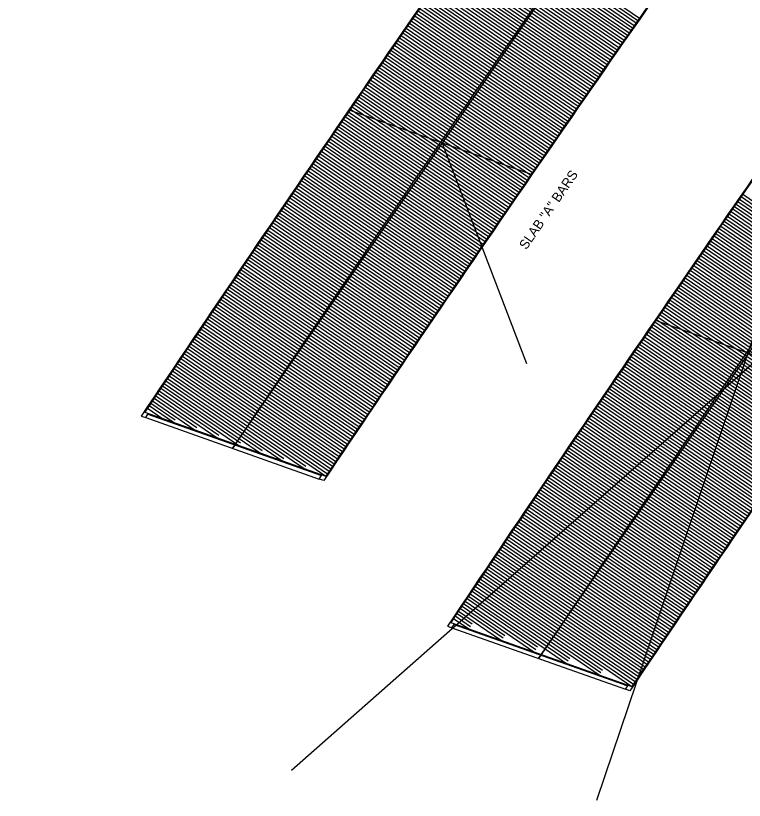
# Model space of a CAD drawing. Extents: x 2378999 to 2381348, y 331302 to 333122.
# Drawn here: x 2379615.5 to 2379768, y 332290.5 to 332454.8 of the extents above; entities that cross this region are included whole.
import ezdxf

# ---------------------------------------------------------------- set-up
doc = ezdxf.new("R2010")
doc.units = 0
for name, color, linetype in [('Mis Work Point CELL', 7, 'Continuous'), ('Old_Level_8', 7, 'Continuous'), ('P_SMU_Concrete_Barrier_Rail', 7, 'Continuous'), ('P_SMU_Mis_Long_Chord', 7, 'Continuous'), ('P_SMU_Rebar_B_Bar', 7, 'Continuous'), ('P_SMU_Rebar_K_Bar', 7, 'Continuous'), ('Plan Sheet CELL', 7, 'Continuous'), ('Scratch_Level_0', 7, 'Continuous'), ('Sup Concrete Slab Lines', 7, 'Continuous'), ('Text', 7, 'Continuous')]:
    doc.layers.add(name, color=color, linetype=linetype)

msp = doc.modelspace()

# ---------------------------------------------------------------- linework, layer by layer
at = {"layer": 'Mis Work Point CELL'}
for p, q in [((2379685.3, 332435.09), (2379723.61, 332421.53)), ((2379749.38, 332391.06), (2379787.69, 332377.5))]:
    msp.add_line(p, q, dxfattribs=at)
at = {"layer": 'Old_Level_8'}
for p, q in [((2379713.66, 332475.82), (2379745.74, 332453.79)), ((2379714.02, 332476.34), (2379746.09, 332454.3)), ((2379712.23, 332473.77), (2379744.31, 332451.73)), ((2379712.59, 332474.28), (2379744.67, 332452.25)), ((2379712.95, 332474.8), (2379745.02, 332452.76)), ((2379713.3, 332475.31), (2379745.38, 332453.27)), ((2379711.16, 332472.23), (2379743.24, 332450.19)), ((2379711.52, 332472.75), (2379743.59, 332450.71)), ((2379711.87, 332473.26), (2379743.95, 332451.22)), ((2379710.09, 332470.69), (2379742.17, 332448.66)), ((2379710.45, 332471.21), (2379742.52, 332449.17)), ((2379710.8, 332471.72), (2379742.88, 332449.68)), ((2379709.02, 332469.15), (2379741.1, 332447.12)), ((2379709.38, 332469.67), (2379741.45, 332447.63)), ((2379709.73, 332470.18), (2379741.81, 332448.14)), ((2379707.95, 332467.61), (2379740.03, 332445.58)), ((2379708.31, 332468.13), (2379740.38, 332446.09)), ((2379708.66, 332468.64), (2379740.74, 332446.6)), ((2379706.53, 332465.56), (2379738.6, 332443.52)), ((2379706.88, 332466.07), (2379738.96, 332444.03)), ((2379707.24, 332466.59), (2379739.31, 332444.55)), ((2379707.6, 332467.1), (2379739.67, 332445.06)), ((2379705.46, 332464.02), (2379737.53, 332441.98)), ((2379705.81, 332464.53), (2379737.89, 332442.49)), ((2379706.17, 332465.05), (2379738.25, 332443.01)), ((2379704.39, 332462.48), (2379736.47, 332440.44)), ((2379704.75, 332462.99), (2379736.82, 332440.95)), ((2379705.1, 332463.5), (2379737.18, 332441.47)), ((2379703.32, 332460.94), (2379735.4, 332438.9)), ((2379703.68, 332461.45), (2379735.75, 332439.41)), ((2379704.03, 332461.96), (2379736.11, 332439.93)), ((2379702.25, 332459.39), (2379734.33, 332437.36)), ((2379702.61, 332459.91), (2379734.69, 332437.87)), ((2379702.97, 332460.42), (2379735.04, 332438.38)), ((2379700.83, 332457.34), (2379732.91, 332435.3)), ((2379701.19, 332457.85), (2379733.26, 332435.81)), ((2379701.54, 332458.37), (2379733.62, 332436.33)), ((2379701.9, 332458.88), (2379733.98, 332436.84)), ((2379699.77, 332455.8), (2379731.84, 332433.76)), ((2379700.12, 332456.31), (2379732.2, 332434.27)), ((2379700.48, 332456.82), (2379732.55, 332434.79)), ((2379698.7, 332454.25), (2379730.78, 332432.22)), ((2379699.06, 332454.77), (2379731.13, 332432.73)), ((2379699.41, 332455.28), (2379731.49, 332433.24)), ((2379697.63, 332452.71), (2379729.71, 332430.67)), ((2379697.99, 332453.22), (2379730.07, 332431.19)), ((2379698.34, 332453.74), (2379730.42, 332431.7)), ((2379696.57, 332451.17), (2379728.65, 332429.13)), ((2379696.92, 332451.68), (2379729, 332429.64)), ((2379697.28, 332452.2), (2379729.36, 332430.16)), ((2379695.15, 332449.11), (2379727.23, 332427.07)), ((2379695.5, 332449.62), (2379727.58, 332427.59)), ((2379695.86, 332450.14), (2379727.94, 332428.1)), ((2379696.21, 332450.65), (2379728.29, 332428.62)), ((2379694.09, 332447.57), (2379726.16, 332425.53)), ((2379694.44, 332448.08), (2379726.52, 332426.04)), ((2379694.8, 332448.59), (2379726.87, 332426.56)), ((2379693.02, 332446.02), (2379725.1, 332423.98)), ((2379693.38, 332446.54), (2379725.45, 332424.5)), ((2379693.73, 332447.05), (2379725.81, 332425.01)), ((2379691.96, 332444.48), (2379724.03, 332422.44)), ((2379692.31, 332444.99), (2379724.39, 332422.95)), ((2379692.67, 332445.51), (2379724.74, 332423.47)), ((2379690.9, 332442.93), (2379722.97, 332420.9)), ((2379691.25, 332443.45), (2379723.33, 332421.41)), ((2379691.6, 332443.96), (2379723.68, 332421.93)), ((2379689.48, 332440.87), (2379721.56, 332418.84)), ((2379689.83, 332441.39), (2379721.91, 332419.35)), ((2379690.19, 332441.9), (2379722.26, 332419.87)), ((2379690.54, 332442.42), (2379722.62, 332420.38)), ((2379688.42, 332439.33), (2379720.49, 332417.29)), ((2379688.77, 332439.84), (2379720.85, 332417.81)), ((2379689.13, 332440.36), (2379721.2, 332418.32)), ((2379687.36, 332437.78), (2379719.43, 332415.74)), ((2379687.71, 332438.3), (2379719.79, 332416.26)), ((2379688.06, 332438.81), (2379720.14, 332416.77)), ((2379686.29, 332436.24), (2379718.37, 332414.2)), ((2379686.65, 332436.75), (2379718.72, 332414.71)), ((2379687, 332437.27), (2379719.08, 332415.23)), ((2379685.23, 332434.69), (2379717.31, 332412.65)), ((2379685.59, 332435.21), (2379717.66, 332413.17)), ((2379685.94, 332435.72), (2379718.02, 332413.68)), ((2379684.17, 332433.14), (2379716.25, 332411.11)), ((2379684.53, 332433.66), (2379716.6, 332411.62)), ((2379684.88, 332434.17), (2379716.96, 332412.14)), ((2379682.76, 332431.08), (2379714.84, 332409.04)), ((2379683.11, 332431.6), (2379715.19, 332409.56)), ((2379683.47, 332432.11), (2379715.54, 332410.08)), ((2379683.82, 332432.63), (2379715.9, 332410.59)), ((2379681.7, 332429.53), (2379713.78, 332407.5)), ((2379682.05, 332430.05), (2379714.13, 332408.01)), ((2379682.41, 332430.57), (2379714.48, 332408.53)), ((2379680.64, 332427.99), (2379712.72, 332405.95)), ((2379681, 332428.5), (2379713.07, 332406.47)), ((2379681.35, 332429.02), (2379713.42, 332406.98)), ((2379679.58, 332426.44), (2379711.66, 332404.4)), ((2379679.94, 332426.96), (2379712.01, 332404.92)), ((2379680.29, 332427.47), (2379712.37, 332405.43)), ((2379678.53, 332424.89), (2379710.6, 332402.85)), ((2379678.88, 332425.41), (2379710.95, 332403.37)), ((2379679.23, 332425.92), (2379711.31, 332403.89)), ((2379677.12, 332422.83), (2379709.19, 332400.79)), ((2379677.47, 332423.34), (2379709.54, 332401.31)), ((2379677.82, 332423.86), (2379709.9, 332401.82)), ((2379678.17, 332424.38), (2379710.25, 332402.34)), ((2379676.06, 332421.28), (2379708.13, 332399.24)), ((2379676.41, 332421.79), (2379708.49, 332399.76)), ((2379676.76, 332422.31), (2379708.84, 332400.27)), ((2379675, 332419.73), (2379707.08, 332397.69)), ((2379675.35, 332420.25), (2379707.43, 332398.21)), ((2379675.71, 332420.76), (2379707.78, 332398.72)), ((2379673.94, 332418.18), (2379706.02, 332396.14)), ((2379674.3, 332418.7), (2379706.37, 332396.66)), ((2379674.65, 332419.21), (2379706.73, 332397.18)), ((2379672.89, 332416.63), (2379704.96, 332394.59)), ((2379673.24, 332417.15), (2379705.32, 332395.11)), ((2379673.59, 332417.66), (2379705.67, 332395.63)), ((2379767.04, 332416.38), (2379799.11, 332394.34)), ((2379767.39, 332416.9), (2379799.47, 332394.86)), ((2379767.75, 332417.41), (2379799.82, 332395.37)), ((2379671.83, 332415.08), (2379703.91, 332393.04)), ((2379672.19, 332415.6), (2379704.26, 332393.56)), ((2379672.54, 332416.11), (2379704.61, 332394.08)), ((2379765.97, 332414.84), (2379798.04, 332392.8)), ((2379766.32, 332415.35), (2379798.4, 332393.32)), ((2379766.68, 332415.87), (2379798.76, 332393.83)), ((2379670.43, 332413.01), (2379702.5, 332390.98)), ((2379670.78, 332413.53), (2379702.85, 332391.49)), ((2379671.13, 332414.05), (2379703.21, 332392.01)), ((2379671.48, 332414.56), (2379703.56, 332392.53)), ((2379764.9, 332413.3), (2379796.98, 332391.26)), ((2379765.26, 332413.81), (2379797.33, 332391.77)), ((2379765.61, 332414.33), (2379797.69, 332392.29)), ((2379669.37, 332411.46), (2379701.45, 332389.43)), ((2379669.72, 332411.98), (2379701.8, 332389.94)), ((2379670.07, 332412.5), (2379702.15, 332390.46)), ((2379763.84, 332411.76), (2379795.91, 332389.72)), ((2379764.19, 332412.27), (2379796.27, 332390.23)), ((2379764.55, 332412.78), (2379796.62, 332390.75)), ((2379668.32, 332409.91), (2379700.39, 332387.88)), ((2379668.67, 332410.43), (2379700.75, 332388.39)), ((2379669.02, 332410.95), (2379701.1, 332388.91)), ((2379762.41, 332409.7), (2379794.49, 332387.66)), ((2379762.77, 332410.21), (2379794.85, 332388.18)), ((2379763.12, 332410.73), (2379795.2, 332388.69)), ((2379763.48, 332411.24), (2379795.56, 332389.2)), ((2379667.26, 332408.36), (2379699.34, 332386.33)), ((2379667.62, 332408.88), (2379699.69, 332386.84)), ((2379667.97, 332409.4), (2379700.04, 332387.36)), ((2379761.35, 332408.16), (2379793.42, 332386.12)), ((2379761.7, 332408.67), (2379793.78, 332386.63)), ((2379762.06, 332409.19), (2379794.14, 332387.15)), ((2379666.21, 332406.81), (2379698.29, 332384.77)), ((2379666.56, 332407.33), (2379698.64, 332385.29)), ((2379666.91, 332407.85), (2379698.99, 332385.81)), ((2379760.28, 332406.61), (2379792.36, 332384.58)), ((2379760.64, 332407.13), (2379792.71, 332385.09)), ((2379760.99, 332407.64), (2379793.07, 332385.6)), ((2379664.81, 332404.74), (2379696.88, 332382.71)), ((2379665.16, 332405.26), (2379697.23, 332383.22)), ((2379665.51, 332405.78), (2379697.58, 332383.74)), ((2379665.86, 332406.29), (2379697.94, 332384.26)), ((2379759.22, 332405.07), (2379791.3, 332383.03)), ((2379759.57, 332405.58), (2379791.65, 332383.55)), ((2379759.93, 332406.1), (2379792.01, 332384.06)), ((2379663.75, 332403.19), (2379695.83, 332381.15)), ((2379664.1, 332403.71), (2379696.18, 332381.67)), ((2379664.46, 332404.23), (2379696.53, 332382.19)), ((2379758.16, 332403.53), (2379790.23, 332381.49)), ((2379758.51, 332404.04), (2379790.59, 332382)), ((2379758.86, 332404.56), (2379790.94, 332382.52)), ((2379662.7, 332401.64), (2379694.78, 332379.6)), ((2379663.05, 332402.16), (2379695.13, 332380.12)), ((2379663.4, 332402.67), (2379695.48, 332380.64)), ((2379756.74, 332401.47), (2379788.81, 332379.43)), ((2379757.09, 332401.98), (2379789.17, 332379.94)), ((2379757.45, 332402.5), (2379789.52, 332380.46)), ((2379757.8, 332403.01), (2379789.88, 332380.97)), ((2379661.65, 332400.09), (2379693.73, 332378.05)), ((2379662, 332400.6), (2379694.08, 332378.57)), ((2379662.35, 332401.12), (2379694.43, 332379.08)), ((2379755.67, 332399.92), (2379787.75, 332377.89)), ((2379756.03, 332400.44), (2379788.1, 332378.4)), ((2379756.38, 332400.95), (2379788.46, 332378.91)), ((2379660.6, 332398.53), (2379692.68, 332376.5)), ((2379660.95, 332399.05), (2379693.03, 332377.01)), ((2379661.3, 332399.57), (2379693.38, 332377.53)), ((2379754.61, 332398.38), (2379786.69, 332376.34)), ((2379754.97, 332398.89), (2379787.04, 332376.86)), ((2379755.32, 332399.41), (2379787.4, 332377.37)), ((2379659.55, 332396.98), (2379691.63, 332374.94)), ((2379659.9, 332397.5), (2379691.98, 332375.46)), ((2379660.25, 332398.02), (2379692.33, 332375.98)), ((2379753.55, 332396.83), (2379785.62, 332374.8)), ((2379753.9, 332397.35), (2379785.98, 332375.31)), ((2379754.26, 332397.86), (2379786.33, 332375.83)), ((2379658.15, 332394.91), (2379690.22, 332372.87)), ((2379658.5, 332395.43), (2379690.57, 332373.39)), ((2379658.85, 332395.95), (2379690.92, 332373.91)), ((2379659.2, 332396.46), (2379691.27, 332374.43)), ((2379752.49, 332395.29), (2379784.56, 332373.25)), ((2379752.84, 332395.8), (2379784.92, 332373.77)), ((2379753.19, 332396.32), (2379785.27, 332374.28)), ((2379657.1, 332393.36), (2379689.17, 332371.32)), ((2379657.45, 332393.87), (2379689.52, 332371.84)), ((2379657.8, 332394.39), (2379689.87, 332372.35)), ((2379751.07, 332393.23), (2379783.15, 332371.19)), ((2379751.43, 332393.74), (2379783.5, 332371.7)), ((2379751.78, 332394.26), (2379783.85, 332372.22)), ((2379752.13, 332394.77), (2379784.21, 332372.74)), ((2379656.05, 332391.8), (2379688.13, 332369.76)), ((2379656.4, 332392.32), (2379688.48, 332370.28)), ((2379656.75, 332392.84), (2379688.83, 332370.8)), ((2379750.01, 332391.68), (2379782.09, 332369.64)), ((2379750.36, 332392.2), (2379782.44, 332370.16)), ((2379750.72, 332392.71), (2379782.79, 332370.67)), ((2379655, 332390.25), (2379687.08, 332368.21)), ((2379655.35, 332390.77), (2379687.43, 332368.73)), ((2379655.7, 332391.28), (2379687.78, 332369.25)), ((2379748.95, 332390.13), (2379781.03, 332368.1)), ((2379749.3, 332390.65), (2379781.38, 332368.61)), ((2379749.66, 332391.17), (2379781.73, 332369.13)), ((2379653.95, 332388.69), (2379686.03, 332366.66)), ((2379654.3, 332389.21), (2379686.38, 332367.17)), ((2379654.65, 332389.73), (2379686.73, 332367.69)), ((2379747.89, 332388.59), (2379779.97, 332366.55)), ((2379748.24, 332389.1), (2379780.32, 332367.07)), ((2379748.6, 332389.62), (2379780.67, 332367.58)), ((2379652.9, 332387.14), (2379684.98, 332365.1)), ((2379653.25, 332387.66), (2379685.33, 332365.62)), ((2379653.6, 332388.18), (2379685.68, 332366.14)), ((2379746.83, 332387.04), (2379778.91, 332365)), ((2379747.18, 332387.56), (2379779.26, 332365.52)), ((2379747.54, 332388.07), (2379779.61, 332366.04)), ((2379651.51, 332385.07), (2379683.58, 332363.03)), ((2379651.86, 332385.58), (2379683.93, 332363.55)), ((2379652.2, 332386.1), (2379684.28, 332364.06)), ((2379652.55, 332386.62), (2379684.63, 332364.58)), ((2379745.77, 332385.49), (2379777.85, 332363.46)), ((2379746.12, 332386.01), (2379778.2, 332363.97)), ((2379746.48, 332386.53), (2379778.55, 332364.49)), ((2379650.46, 332383.51), (2379682.54, 332361.47)), ((2379650.81, 332384.03), (2379682.88, 332361.99)), ((2379651.16, 332384.55), (2379683.23, 332362.51)), ((2379744.36, 332383.43), (2379776.43, 332361.39)), ((2379744.71, 332383.95), (2379776.79, 332361.91)), ((2379745.06, 332384.46), (2379777.14, 332362.43)), ((2379745.42, 332384.98), (2379777.49, 332362.94)), ((2379649.41, 332381.96), (2379681.49, 332359.92)), ((2379649.76, 332382.47), (2379681.84, 332360.44)), ((2379650.11, 332382.99), (2379682.19, 332360.95)), ((2379743.3, 332381.88), (2379775.38, 332359.85)), ((2379743.65, 332382.4), (2379775.73, 332360.36)), ((2379744.01, 332382.92), (2379776.08, 332360.88)), ((2379648.37, 332380.4), (2379680.44, 332358.36)), ((2379648.71, 332380.92), (2379680.79, 332358.88)), ((2379649.06, 332381.44), (2379681.14, 332359.4)), ((2379742.24, 332380.34), (2379774.32, 332358.3)), ((2379742.59, 332380.85), (2379774.67, 332358.81)), ((2379742.95, 332381.37), (2379775.02, 332359.33)), ((2379647.32, 332378.84), (2379671.69, 332362.1)), ((2379647.67, 332379.36), (2379675.89, 332359.97)), ((2379648.03, 332379.87), (2379676.24, 332360.49)), ((2379741.18, 332378.79), (2379773.26, 332356.75)), ((2379741.54, 332379.3), (2379773.61, 332357.27)), ((2379741.89, 332379.82), (2379773.97, 332357.78)), ((2379646.27, 332377.29), (2379666.78, 332363.2)), ((2379646.63, 332377.8), (2379667.14, 332363.71)), ((2379646.98, 332378.32), (2379671.33, 332361.59)), ((2379740.13, 332377.24), (2379772.2, 332355.2)), ((2379740.48, 332377.76), (2379772.56, 332355.72)), ((2379740.83, 332378.27), (2379772.91, 332356.23)), ((2379644.89, 332375.2), (2379657.68, 332366.42)), ((2379645.23, 332375.73), (2379658.03, 332366.94)), ((2379645.58, 332376.25), (2379662.23, 332364.81)), ((2379645.94, 332376.76), (2379662.58, 332365.32)), ((2379738.72, 332375.17), (2379770.79, 332353.14)), ((2379739.07, 332375.69), (2379771.15, 332353.65)), ((2379739.42, 332376.21), (2379771.5, 332354.17)), ((2379739.78, 332376.72), (2379771.85, 332354.69)), ((2379643.85, 332373.65), (2379648.92, 332370.16)), ((2379644.18, 332374.17), (2379653.12, 332368.03)), ((2379644.54, 332374.69), (2379653.48, 332368.55)), ((2379737.66, 332373.62), (2379769.74, 332351.59)), ((2379738.01, 332374.14), (2379770.09, 332352.1)), ((2379738.37, 332374.66), (2379770.44, 332352.62)), ((2379643.14, 332372.62), (2379646.29, 332370.45)), ((2379643.49, 332373.13), (2379648.57, 332369.64)), ((2379736.61, 332372.07), (2379768.68, 332350.04)), ((2379736.96, 332372.59), (2379769.03, 332350.55)), ((2379737.31, 332373.11), (2379769.39, 332351.07)), ((2379735.55, 332370.53), (2379767.63, 332348.49)), ((2379735.9, 332371.04), (2379767.98, 332349)), ((2379736.25, 332371.56), (2379768.33, 332349.52)), ((2379734.5, 332368.98), (2379766.57, 332346.94)), ((2379734.85, 332369.49), (2379766.92, 332347.45)), ((2379735.2, 332370.01), (2379767.28, 332347.97)), ((2379733.44, 332367.42), (2379765.52, 332345.39)), ((2379733.79, 332367.94), (2379765.87, 332345.9)), ((2379734.14, 332368.46), (2379766.22, 332346.42)), ((2379732.04, 332365.36), (2379764.11, 332343.32)), ((2379732.39, 332365.87), (2379764.46, 332343.84)), ((2379732.74, 332366.39), (2379764.81, 332344.35)), ((2379733.09, 332366.91), (2379765.17, 332344.87)), ((2379730.98, 332363.81), (2379763.06, 332341.77)), ((2379731.33, 332364.32), (2379763.41, 332342.29)), ((2379731.68, 332364.84), (2379763.76, 332342.8)), ((2379729.93, 332362.26), (2379762.01, 332340.22)), ((2379730.28, 332362.77), (2379762.36, 332340.73)), ((2379730.63, 332363.29), (2379762.71, 332341.25)), ((2379728.88, 332360.7), (2379760.95, 332338.67)), ((2379729.23, 332361.22), (2379761.3, 332339.18)), ((2379729.58, 332361.74), (2379761.65, 332339.7)), ((2379727.82, 332359.15), (2379759.9, 332337.11)), ((2379728.17, 332359.67), (2379760.25, 332337.63)), ((2379728.53, 332360.19), (2379760.6, 332338.15)), ((2379726.42, 332357.08), (2379758.5, 332335.04)), ((2379726.77, 332357.6), (2379758.85, 332335.56)), ((2379727.12, 332358.12), (2379759.2, 332336.08)), ((2379727.47, 332358.63), (2379759.55, 332336.6)), ((2379725.37, 332355.53), (2379757.45, 332333.49)), ((2379725.72, 332356.05), (2379757.8, 332334.01)), ((2379726.07, 332356.56), (2379758.15, 332334.53)), ((2379724.32, 332353.98), (2379756.4, 332331.94)), ((2379724.67, 332354.49), (2379756.75, 332332.46)), ((2379725.02, 332355.01), (2379757.1, 332332.97)), ((2379723.27, 332352.42), (2379755.34, 332330.39)), ((2379723.62, 332352.94), (2379755.69, 332330.9)), ((2379723.97, 332353.46), (2379756.04, 332331.42)), ((2379722.22, 332350.87), (2379754.29, 332328.83)), ((2379722.57, 332351.39), (2379754.64, 332329.35)), ((2379722.92, 332351.91), (2379754.99, 332329.87)), ((2379721.17, 332349.32), (2379753.24, 332327.28)), ((2379721.52, 332349.83), (2379753.59, 332327.8)), ((2379721.87, 332350.35), (2379753.94, 332328.31)), ((2379719.77, 332347.25), (2379751.85, 332325.21)), ((2379720.12, 332347.76), (2379752.2, 332325.73)), ((2379720.47, 332348.28), (2379752.54, 332326.24)), ((2379720.82, 332348.8), (2379752.89, 332326.76)), ((2379718.72, 332345.69), (2379750.8, 332323.65)), ((2379719.07, 332346.21), (2379751.15, 332324.17)), ((2379719.42, 332346.73), (2379751.5, 332324.69)), ((2379717.67, 332344.14), (2379749.75, 332322.1)), ((2379718.02, 332344.65), (2379750.1, 332322.62)), ((2379718.37, 332345.17), (2379750.45, 332323.13)), ((2379716.62, 332342.58), (2379748.7, 332320.54)), ((2379716.97, 332343.1), (2379749.05, 332321.06)), ((2379717.32, 332343.62), (2379749.4, 332321.58)), ((2379715.58, 332341.03), (2379747.65, 332318.99)), ((2379715.92, 332341.54), (2379748, 332319.51)), ((2379716.27, 332342.06), (2379748.35, 332320.02)), ((2379714.53, 332339.47), (2379746.61, 332317.43)), ((2379714.88, 332339.99), (2379746.95, 332317.95)), ((2379715.23, 332340.51), (2379747.3, 332318.47)), ((2379713.13, 332337.4), (2379745.21, 332315.36)), ((2379713.48, 332337.92), (2379745.56, 332315.88)), ((2379713.83, 332338.43), (2379745.91, 332316.4)), ((2379714.18, 332338.95), (2379746.26, 332316.91)), ((2379712.1, 332335.83), (2379738.39, 332317.77)), ((2379712.43, 332336.36), (2379744.51, 332314.32)), ((2379712.78, 332336.88), (2379744.86, 332314.84)), ((2379711.05, 332334.28), (2379731.56, 332320.19)), ((2379711.39, 332334.8), (2379737.68, 332316.74)), ((2379711.74, 332335.32), (2379738.03, 332317.26)), ((2379710.01, 332332.72), (2379724.73, 332322.6)), ((2379710.34, 332333.25), (2379730.85, 332319.16)), ((2379710.7, 332333.76), (2379731.2, 332319.67)), ((2379708.96, 332331.16), (2379717.9, 332325.02)), ((2379709.3, 332331.69), (2379724.02, 332321.57)), ((2379709.65, 332332.21), (2379724.38, 332322.09)), ((2379707.92, 332329.61), (2379711.07, 332327.44)), ((2379708.25, 332330.13), (2379717.19, 332323.99)), ((2379708.61, 332330.65), (2379717.55, 332324.51)), ((2379707.21, 332328.58), (2379710.36, 332326.41)), ((2379707.56, 332329.09), (2379710.72, 332326.92))]:
    msp.add_line(p, q, dxfattribs=at)
at = {"layer": 'P_SMU_Concrete_Barrier_Rail'}
for p, q in [((2379641.82, 332370.95), (2379642.76, 332370.62)), ((2379642.76, 332370.62), (2379643.23, 332371.34)), ((2379643.23, 332371.34), (2379679.57, 332358.48)), ((2379643.88, 332371.11), (2379643.23, 332371.34)), ((2379678.92, 332358.71), (2379679.57, 332358.48)), ((2379679.09, 332357.76), (2379679.57, 332358.48)), ((2379680.02, 332357.43), (2379679.09, 332357.76)), ((2379705.9, 332326.93), (2379706.84, 332326.6)), ((2379706.84, 332326.6), (2379707.31, 332327.31)), ((2379707.31, 332327.31), (2379743.65, 332314.45)), ((2379707.96, 332327.08), (2379707.31, 332327.31)), ((2379743, 332314.68), (2379743.65, 332314.45)), ((2379743.17, 332313.74), (2379743.65, 332314.45)), ((2379744.1, 332313.41), (2379743.17, 332313.74))]:
    msp.add_line(p, q, dxfattribs=at)
for centre, radius, start, end in [((2385539.92, 328419.1), 7099.63, 144.926438, 146.177079), ((2385539.92, 328419.1), 7060.38, 144.837589, 146.095684), ((2385604, 328375.08), 7099.63, 144.926438, 146.177079), ((2385604, 328375.08), 7060.38, 144.837589, 146.095684)]:
    msp.add_arc(centre, radius, start, end, dxfattribs=at)
at = {"layer": 'P_SMU_Mis_Long_Chord'}
for centre, start, end in [((2385442.05, 328467.93), 144.405564, 146.828556), ((2385539.92, 328419.1), 144.882142, 146.136498), ((2385604, 328375.08), 144.882142, 146.136498)]:
    msp.add_arc(centre, 7080, start, end, dxfattribs=at)
at = {"layer": 'P_SMU_Rebar_B_Bar'}
for p, q in [((2379642.76, 332370.62), (2379679.09, 332357.76)), ((2379706.84, 332326.6), (2379743.17, 332313.74))]:
    msp.add_line(p, q, dxfattribs=at)
at = {"layer": 'P_SMU_Rebar_K_Bar'}
msp.add_line((2379704.8, 332428.07), (2379722.49, 332381.97), dxfattribs=at)
at = {"layer": 'Plan Sheet CELL'}
for p, q in [((2379660.92, 332364.19), (2379748.69, 332491.94)), ((2379725, 332320.17), (2379812.77, 332447.92))]:
    msp.add_line(p, q, dxfattribs=at)
at = {"layer": 'Scratch_Level_0'}
for p, q in [((2379642.57, 332371.77), (2379680.44, 332358.36)), ((2379706.64, 332327.73), (2379744.51, 332314.32))]:
    msp.add_line(p, q, dxfattribs=at)
for centre, radius, start, end in [((2385539.92, 328419.1), 7099.46, 144.934441, 146.168406), ((2385539.92, 328419.1), 7060.54, 144.846397, 146.087653), ((2385604, 328375.08), 7099.46, 144.934441, 146.168406), ((2385604, 328375.08), 7060.54, 144.846397, 146.087653)]:
    msp.add_arc(centre, radius, start, end, dxfattribs=at)
at = {"layer": 'Text'}
for p, q in [((2379737.17, 332290.49), (2379803.09, 332485.73)), ((2379850.55, 332453.13), (2379673.26, 332296.76))]:
    msp.add_line(p, q, dxfattribs=at)

# ---------------------------------------------------------------- texts
at = {"layer": 'Sup Concrete Slab Lines'}
msp.add_text('SLAB "A" BARS', height=2, rotation=55.5093, dxfattribs=at).set_placement((2379722.41, 332405.65))

doc.saveas('drawing.dxf')
